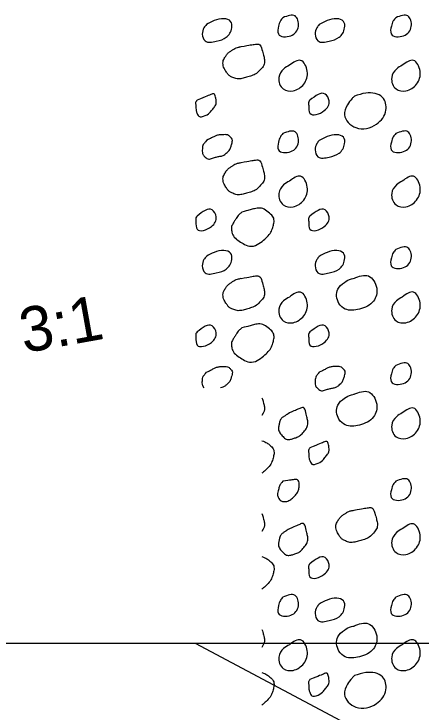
# Model space of a CAD drawing. Extents: x 0 to 2765, y 0 to 220.
# Drawn here: x 148.05 to 160.8, y 145.04 to 166.91 of the extents above; entities that cross this region are included whole.
import ezdxf

# ---------------------------------------------------------------- set-up
doc = ezdxf.new("R2010")
doc.units = 0
for name, color, linetype in [('MT_P_Stop_Line', 7, 'Continuous'), ('MT_P_Work_Area', 7, 'Continuous'), ('XS_P_Finished_Grade', 7, 'Continuous')]:
    doc.layers.add(name, color=color, linetype=linetype)

msp = doc.modelspace()

# ---------------------------------------------------------------- linework, layer by layer
at = {"layer": 'MT_P_Stop_Line'}
for points in [[(156.478, 166.793), (156.859, 166.849), (156.963, 166.52), (156.723, 166.226), (156.337, 166.283), (156.339, 166.529), (156.398, 166.692), (156.478, 166.793)], [(160.013, 166.793), (160.395, 166.849), (160.499, 166.52), (160.259, 166.226), (159.872, 166.283), (159.875, 166.529), (159.933, 166.692), (160.013, 166.793)], [(154.079, 166.576), (154.329, 166.701), (154.63, 166.759), (154.841, 166.678), (154.875, 166.474), (154.704, 166.178), (154.391, 166.058), (154.039, 166.064), (153.953, 166.279), (154.005, 166.479), (154.079, 166.576)], [(157.615, 166.576), (157.865, 166.701), (158.166, 166.759), (158.377, 166.678), (158.411, 166.474), (158.24, 166.178), (157.927, 166.058), (157.575, 166.064), (157.489, 166.279), (157.541, 166.479), (157.615, 166.576)], [(156.682, 165.304), (157.033, 165.455), (157.241, 165.117), (157.129, 164.712), (156.796, 164.499), (156.485, 164.559), (156.352, 164.918), (156.498, 165.185), (156.682, 165.304)], [(160.217, 165.304), (160.569, 165.455), (160.777, 165.117), (160.665, 164.712), (160.332, 164.499), (160.021, 164.559), (159.887, 164.918), (160.033, 165.185), (160.217, 165.304)], [(157.323, 164.209), (157.798, 164.402), (157.924, 164.184), (157.775, 163.881), (157.325, 163.797), (157.286, 164.037), (157.29, 164.158), (157.323, 164.209)], [(158.722, 164.335), (159.078, 164.429), (159.599, 164.297), (159.707, 163.894), (159.411, 163.459), (158.762, 163.349), (158.408, 163.747), (158.503, 164.065), (158.642, 164.258), (158.722, 164.335)], [(156.478, 163.162), (156.859, 163.218), (156.963, 162.89), (156.723, 162.596), (156.337, 162.652), (156.339, 162.898), (156.398, 163.061), (156.478, 163.162)], [(157.615, 162.946), (157.865, 163.071), (158.166, 163.128), (158.377, 163.047), (158.411, 162.844), (158.24, 162.547), (157.927, 162.427), (157.575, 162.433), (157.489, 162.649), (157.541, 162.849), (157.615, 162.946)], [(160.013, 163.162), (160.395, 163.218), (160.499, 162.89), (160.259, 162.596), (159.872, 162.652), (159.875, 162.898), (159.933, 163.061), (160.013, 163.162)], [(156.682, 161.674), (157.033, 161.825), (157.241, 161.486), (157.129, 161.081), (156.796, 160.869), (156.485, 160.928), (156.352, 161.287), (156.498, 161.555), (156.682, 161.674)], [(160.217, 161.674), (160.569, 161.825), (160.777, 161.486), (160.665, 161.081), (160.332, 160.869), (160.021, 160.928), (159.887, 161.287), (160.033, 161.555), (160.217, 161.674)], [(153.788, 160.579), (154.263, 160.771), (154.388, 160.553), (154.239, 160.251), (153.789, 160.166), (153.75, 160.406), (153.754, 160.527), (153.788, 160.579)], [(157.323, 160.579), (157.798, 160.771), (157.924, 160.553), (157.775, 160.251), (157.325, 160.166), (157.286, 160.406), (157.29, 160.527), (157.323, 160.579)], [(160.013, 159.532), (160.395, 159.588), (160.499, 159.259), (160.259, 158.965), (159.872, 159.022), (159.875, 159.268), (159.933, 159.431), (160.013, 159.532)], [(154.079, 159.315), (154.329, 159.44), (154.63, 159.498), (154.841, 159.417), (154.875, 159.213), (154.704, 158.917), (154.391, 158.797), (154.039, 158.803), (153.953, 159.018), (154.005, 159.218), (154.079, 159.315)], [(157.615, 159.315), (157.865, 159.44), (158.166, 159.498), (158.377, 159.417), (158.411, 159.213), (158.24, 158.917), (157.927, 158.797), (157.575, 158.803), (157.489, 159.018), (157.541, 159.218), (157.615, 159.315)], [(158.702, 158.626), (159.156, 158.702), (159.415, 158.322), (159.318, 157.915), (158.872, 157.663), (158.432, 157.665), (158.233, 157.843), (158.197, 158.288), (158.402, 158.502), (158.627, 158.61), (158.71, 158.628)], [(156.682, 158.043), (157.033, 158.194), (157.241, 157.856), (157.129, 157.451), (156.796, 157.238), (156.485, 157.298), (156.352, 157.657), (156.498, 157.924), (156.682, 158.043)], [(160.217, 158.043), (160.569, 158.194), (160.777, 157.856), (160.665, 157.451), (160.332, 157.238), (160.021, 157.298), (159.887, 157.657), (160.033, 157.924), (160.217, 158.043)], [(153.788, 156.948), (154.263, 157.141), (154.388, 156.923), (154.239, 156.62), (153.789, 156.536), (153.75, 156.776), (153.754, 156.897), (153.788, 156.948)], [(157.323, 156.948), (157.798, 157.141), (157.924, 156.923), (157.775, 156.62), (157.325, 156.536), (157.286, 156.776), (157.29, 156.897), (157.323, 156.948)], [(160.013, 155.901), (160.395, 155.957), (160.499, 155.629), (160.259, 155.335), (159.872, 155.391), (159.875, 155.637), (159.933, 155.8), (160.013, 155.901)], [(158.702, 154.995), (159.156, 155.071), (159.415, 154.691), (159.318, 154.285), (158.872, 154.032), (158.432, 154.035), (158.233, 154.213), (158.197, 154.658), (158.402, 154.871), (158.627, 154.98), (158.71, 154.997)], [(160.217, 154.413), (160.569, 154.564), (160.777, 154.225), (160.665, 153.82), (160.332, 153.608), (160.021, 153.667), (159.887, 154.026), (160.033, 154.294), (160.217, 154.413)], [(160.013, 152.271), (160.395, 152.327), (160.499, 151.998), (160.259, 151.704), (159.872, 151.761), (159.875, 152.007), (159.933, 152.17), (160.013, 152.271)], [(160.217, 150.783), (160.569, 150.933), (160.777, 150.595), (160.665, 150.19), (160.332, 149.978), (160.021, 150.037), (159.887, 150.396), (160.033, 150.663), (160.217, 150.783)], [(157.323, 149.688), (157.798, 149.88), (157.924, 149.662), (157.775, 149.359), (157.325, 149.275), (157.286, 149.515), (157.29, 149.636), (157.323, 149.688)], [(156.478, 148.64), (156.859, 148.696), (156.963, 148.368), (156.723, 148.074), (156.337, 148.13), (156.339, 148.376), (156.398, 148.54), (156.478, 148.64)], [(160.013, 148.64), (160.395, 148.696), (160.499, 148.368), (160.259, 148.074), (159.872, 148.13), (159.875, 148.376), (159.933, 148.54), (160.013, 148.64)], [(157.615, 148.424), (157.865, 148.549), (158.166, 148.606), (158.377, 148.525), (158.411, 148.322), (158.24, 148.025), (157.927, 147.905), (157.575, 147.911), (157.489, 148.127), (157.541, 148.327), (157.615, 148.424)], [(158.702, 147.735), (159.156, 147.81), (159.415, 147.43), (159.318, 147.024), (158.872, 146.771), (158.432, 146.774), (158.233, 146.952), (158.197, 147.397), (158.402, 147.61), (158.627, 147.719), (158.71, 147.736)], [(156.682, 147.152), (157.033, 147.303), (157.241, 146.965), (157.129, 146.56), (156.796, 146.347), (156.485, 146.406), (156.352, 146.765), (156.498, 147.033), (156.682, 147.152)], [(160.217, 147.152), (160.569, 147.303), (160.777, 146.965), (160.665, 146.56), (160.332, 146.347), (160.021, 146.406), (159.887, 146.765), (160.033, 147.033), (160.217, 147.152)], [(158.722, 146.183), (159.078, 146.276), (159.599, 146.145), (159.707, 145.742), (159.411, 145.307), (158.762, 145.196), (158.408, 145.595), (158.503, 145.913), (158.642, 146.105), (158.722, 146.183)]]:
    msp.add_spline(points, degree=3, dxfattribs=at)
for points in [[(155.166, 165.887), (155.317, 165.913), (155.469, 165.942), (155.62, 165.963), (155.771, 165.984), (155.841, 165.725), (155.879, 165.583), (155.914, 165.454), (155.891, 165.296), (155.783, 165.176), (155.649, 165.029), (155.501, 164.972), (155.337, 164.924), (155.195, 164.882), (155.037, 164.867), (154.897, 164.926), (154.811, 164.962), (154.749, 165.024), (154.698, 165.104), (154.611, 165.238), (154.585, 165.423), (154.661, 165.549), (154.711, 165.633), (154.779, 165.707), (154.866, 165.763), (154.94, 165.81), (155.01, 165.854), (155.092, 165.871), (155.119, 165.877), (155.147, 165.883), (155.174, 165.889)], [(153.788, 164.209), (153.946, 164.274), (154.104, 164.342), (154.263, 164.402), (154.34, 164.432), (154.381, 164.258), (154.388, 164.184), (154.398, 164.084), (154.321, 163.98), (154.239, 163.881), (154.128, 163.747), (153.847, 163.649), (153.789, 163.797), (153.758, 163.875), (153.753, 163.956), (153.75, 164.037), (153.748, 164.077), (153.733, 164.122), (153.754, 164.158), (153.765, 164.176), (153.777, 164.192), (153.788, 164.209)], [(154.079, 162.946), (154.162, 162.988), (154.246, 163.029), (154.329, 163.071), (154.421, 163.116), (154.53, 163.125), (154.63, 163.128), (154.704, 163.13), (154.774, 163.113), (154.841, 163.047), (154.901, 162.987), (154.893, 162.907), (154.875, 162.844), (154.845, 162.739), (154.806, 162.632), (154.704, 162.547), (154.604, 162.464), (154.498, 162.452), (154.391, 162.427), (154.278, 162.401), (154.149, 162.334), (154.039, 162.433), (153.966, 162.498), (153.951, 162.574), (153.953, 162.649), (153.955, 162.715), (153.963, 162.794), (154.005, 162.849), (154.03, 162.882), (154.054, 162.914), (154.079, 162.946)], [(155.166, 162.256), (155.317, 162.282), (155.469, 162.311), (155.62, 162.332), (155.771, 162.353), (155.841, 162.094), (155.879, 161.952), (155.914, 161.823), (155.891, 161.666), (155.783, 161.546), (155.649, 161.398), (155.501, 161.341), (155.337, 161.293), (155.195, 161.252), (155.037, 161.236), (154.897, 161.296), (154.811, 161.332), (154.749, 161.394), (154.698, 161.474), (154.611, 161.608), (154.585, 161.792), (154.661, 161.919), (154.711, 162.003), (154.779, 162.077), (154.866, 162.132), (154.94, 162.179), (155.01, 162.223), (155.092, 162.241), (155.119, 162.246), (155.147, 162.252), (155.174, 162.258)], [(155.187, 160.705), (155.305, 160.736), (155.424, 160.767), (155.543, 160.798), (155.716, 160.843), (155.89, 160.811), (156.063, 160.666), (156.198, 160.554), (156.206, 160.388), (156.171, 160.264), (156.126, 160.107), (156.027, 159.959), (155.875, 159.829), (155.685, 159.667), (155.421, 159.603), (155.227, 159.718), (155.069, 159.811), (154.903, 159.951), (154.873, 160.116), (154.854, 160.219), (154.907, 160.339), (154.968, 160.435), (155.011, 160.503), (155.049, 160.572), (155.106, 160.627), (155.133, 160.653), (155.16, 160.679), (155.187, 160.705)], [(155.166, 158.626), (155.317, 158.652), (155.469, 158.681), (155.62, 158.702), (155.771, 158.723), (155.841, 158.464), (155.879, 158.322), (155.914, 158.193), (155.891, 158.035), (155.783, 157.915), (155.649, 157.768), (155.501, 157.711), (155.337, 157.663), (155.195, 157.621), (155.037, 157.606), (154.897, 157.665), (154.811, 157.701), (154.749, 157.763), (154.698, 157.843), (154.611, 157.977), (154.585, 158.162), (154.661, 158.288), (154.711, 158.372), (154.779, 158.446), (154.866, 158.502), (154.94, 158.549), (155.01, 158.593), (155.092, 158.61), (155.119, 158.616), (155.147, 158.622), (155.174, 158.628)], [(155.187, 157.074), (155.305, 157.106), (155.424, 157.137), (155.543, 157.168), (155.716, 157.213), (155.89, 157.181), (156.063, 157.036), (156.198, 156.924), (156.206, 156.758), (156.171, 156.633), (156.126, 156.477), (156.027, 156.328), (155.875, 156.198), (155.685, 156.036), (155.421, 155.973), (155.227, 156.088), (155.069, 156.181), (154.903, 156.321), (154.873, 156.486), (154.854, 156.589), (154.907, 156.709), (154.968, 156.804), (155.011, 156.873), (155.049, 156.942), (155.106, 156.997), (155.133, 157.023), (155.16, 157.049), (155.187, 157.074)], [(154.079, 155.685), (154.162, 155.727), (154.246, 155.768), (154.329, 155.81), (154.421, 155.855), (154.53, 155.864), (154.63, 155.867), (154.704, 155.869), (154.774, 155.852), (154.841, 155.786), (154.901, 155.726), (154.893, 155.646), (154.875, 155.583), (154.845, 155.478), (154.806, 155.371), (154.704, 155.286), (154.646, 155.238), (154.587, 155.214), (154.526, 155.197)], [(157.615, 155.685), (157.698, 155.727), (157.781, 155.768), (157.865, 155.81), (157.957, 155.855), (158.066, 155.864), (158.166, 155.867), (158.239, 155.869), (158.31, 155.852), (158.377, 155.786), (158.437, 155.726), (158.429, 155.646), (158.411, 155.583), (158.381, 155.478), (158.342, 155.371), (158.24, 155.286), (158.14, 155.203), (158.034, 155.191), (157.927, 155.166), (157.814, 155.14), (157.685, 155.073), (157.575, 155.172), (157.502, 155.237), (157.487, 155.314), (157.489, 155.388), (157.491, 155.454), (157.499, 155.533), (157.541, 155.588), (157.565, 155.621), (157.59, 155.653), (157.615, 155.685)], [(154.014, 155.197), (153.963, 155.257), (153.952, 155.323), (153.953, 155.388), (153.955, 155.454), (153.963, 155.533), (154.005, 155.588), (154.03, 155.621), (154.054, 155.653), (154.079, 155.685)], [(155.817, 154.889), (155.844, 154.821), (155.864, 154.747), (155.879, 154.691), (155.91, 154.577), (155.896, 154.441), (155.817, 154.328)], [(156.682, 154.413), (156.799, 154.463), (156.916, 154.514), (157.033, 154.564), (157.155, 154.616), (157.214, 154.349), (157.241, 154.225), (157.269, 154.094), (157.235, 153.948), (157.129, 153.82), (157.029, 153.701), (156.916, 153.644), (156.796, 153.608), (156.7, 153.579), (156.579, 153.574), (156.485, 153.667), (156.371, 153.78), (156.329, 153.912), (156.352, 154.026), (156.37, 154.117), (156.412, 154.237), (156.498, 154.294), (156.559, 154.335), (156.62, 154.373), (156.682, 154.413)], [(155.817, 153.539), (155.899, 153.517), (155.981, 153.474), (156.063, 153.405), (156.198, 153.293), (156.206, 153.127), (156.171, 153.003), (156.126, 152.846), (156.027, 152.698), (155.875, 152.568), (155.856, 152.552), (155.837, 152.537), (155.817, 152.523)], [(157.323, 153.318), (157.482, 153.382), (157.64, 153.45), (157.798, 153.51), (157.876, 153.54), (157.917, 153.367), (157.924, 153.292), (157.934, 153.193), (157.857, 153.088), (157.775, 152.99), (157.663, 152.856), (157.383, 152.758), (157.325, 152.905), (157.294, 152.984), (157.289, 153.065), (157.286, 153.145), (157.284, 153.186), (157.269, 153.23), (157.29, 153.266), (157.301, 153.285), (157.312, 153.301), (157.323, 153.318)], [(156.478, 152.271), (156.605, 152.289), (156.732, 152.309), (156.859, 152.327), (156.973, 152.342), (156.999, 152.097), (156.963, 151.998), (156.924, 151.89), (156.825, 151.782), (156.723, 151.704), (156.618, 151.624), (156.397, 151.637), (156.337, 151.761), (156.298, 151.839), (156.318, 151.929), (156.339, 152.007), (156.354, 152.062), (156.362, 152.125), (156.398, 152.17), (156.424, 152.204), (156.451, 152.237), (156.478, 152.271)], [(158.702, 151.365), (158.853, 151.391), (159.004, 151.42), (159.156, 151.441), (159.307, 151.462), (159.377, 151.203), (159.415, 151.061), (159.449, 150.932), (159.427, 150.775), (159.318, 150.654), (159.185, 150.507), (159.037, 150.45), (158.872, 150.402), (158.731, 150.36), (158.573, 150.345), (158.432, 150.404), (158.347, 150.44), (158.285, 150.502), (158.233, 150.583), (158.147, 150.716), (158.121, 150.901), (158.197, 151.028), (158.247, 151.111), (158.315, 151.185), (158.402, 151.241), (158.475, 151.288), (158.546, 151.332), (158.627, 151.349), (158.655, 151.355), (158.682, 151.361), (158.71, 151.367)], [(155.817, 151.258), (155.844, 151.19), (155.864, 151.117), (155.879, 151.061), (155.91, 150.947), (155.896, 150.81), (155.817, 150.697)], [(156.682, 150.783), (156.799, 150.833), (156.916, 150.883), (157.033, 150.933), (157.155, 150.985), (157.214, 150.719), (157.241, 150.595), (157.269, 150.464), (157.235, 150.317), (157.129, 150.19), (157.029, 150.07), (156.916, 150.014), (156.796, 149.978), (156.7, 149.949), (156.579, 149.944), (156.485, 150.037), (156.371, 150.149), (156.329, 150.281), (156.352, 150.396), (156.37, 150.487), (156.412, 150.607), (156.498, 150.663), (156.559, 150.704), (156.62, 150.743), (156.682, 150.783)], [(155.817, 149.909), (155.899, 149.887), (155.981, 149.844), (156.063, 149.775), (156.198, 149.663), (156.206, 149.497), (156.171, 149.373), (156.126, 149.216), (156.027, 149.067), (155.875, 148.938), (155.856, 148.921), (155.837, 148.906), (155.817, 148.892)], [(155.817, 147.628), (155.844, 147.56), (155.864, 147.486), (155.879, 147.43), (155.91, 147.316), (155.896, 147.18), (155.817, 147.067)], [(155.817, 146.278), (155.899, 146.256), (155.981, 146.213), (156.063, 146.145), (156.198, 146.032), (156.206, 145.866), (156.171, 145.742), (156.126, 145.585), (156.027, 145.437), (155.875, 145.307), (155.856, 145.291), (155.837, 145.276), (155.817, 145.262)], [(157.323, 146.057), (157.482, 146.121), (157.64, 146.189), (157.798, 146.25), (157.876, 146.279), (157.917, 146.106), (157.924, 146.031), (157.934, 145.932), (157.857, 145.827), (157.775, 145.729), (157.663, 145.595), (157.383, 145.497), (157.325, 145.645), (157.294, 145.723), (157.289, 145.804), (157.286, 145.885), (157.284, 145.925), (157.269, 145.969), (157.29, 146.005), (157.301, 146.024), (157.312, 146.04), (157.323, 146.057)]]:
    msp.add_open_spline(points, degree=3, dxfattribs=at)
at = {"layer": 'MT_P_Work_Area'}
msp.add_line((99.983, 147.197), (167.983, 147.197), dxfattribs=at)
at = {"layer": 'XS_P_Finished_Grade'}
msp.add_line((153.733, 147.197), (188.46, 128.769), dxfattribs=at)

# ---------------------------------------------------------------- texts
msp.add_text('3:1', height=1.4, rotation=10.1636, dxfattribs=at).set_placement((148.365, 156.283))

doc.saveas('drawing.dxf')
